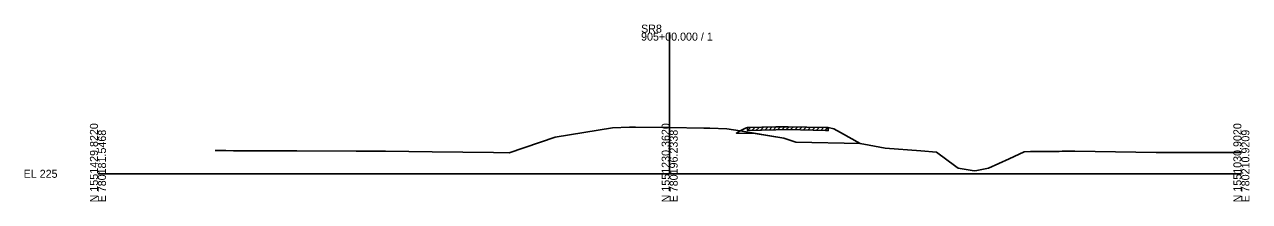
# Model space of a CAD drawing. Extents: x -26 to 787523, y -10 to 1545496.
# Drawn here: x -25.7 to 402.8, y 9990.3 to 10052.2 of the extents above; entities that cross this region are included whole.
import ezdxf

# ---------------------------------------------------------------- set-up
doc = ezdxf.new("R2010")
doc.units = 0
for name, color, linetype in [('50', 7, 'Continuous'), ('XS_CELL', 7, 'Continuous'), ('XS_M_SHAPES_EARTHWORK', 7, 'Continuous'), ('XS_P_FINISHED_GRADE', 7, 'Continuous'), ('XS_P_SUBGRADE_GRANULAR', 7, 'Continuous'), ('XS_X_GROUND', 7, 'Continuous')]:
    doc.layers.add(name, color=color, linetype=linetype)

msp = doc.modelspace()

# ---------------------------------------------------------------- linework, layer by layer
at = {"layer": '50'}
for p, q in [((227.24, 10015.13), (228.27, 10016.15)), ((227.24, 10015.13), (227.24, 10016.13)), ((227.24, 10015.13), (237.17, 10015.36)), ((228.74, 10015.16), (229.77, 10016.19)), ((230.25, 10015.2), (231.28, 10016.22)), ((231.75, 10015.23), (232.78, 10016.26)), ((233.26, 10015.27), (234.29, 10016.29)), ((234.76, 10015.3), (235.79, 10016.32)), ((236.27, 10015.33), (237.3, 10016.36)), ((237.17, 10015.36), (241.48, 10015.45)), ((237.78, 10015.37), (238.8, 10016.39)), ((239.28, 10015.4), (240.31, 10016.43)), ((240.79, 10015.44), (241.8, 10016.45)), ((241.48, 10015.45), (254.57, 10015.15)), ((242.29, 10015.43), (243.27, 10016.41)), ((243.8, 10015.4), (244.78, 10016.38)), ((245.3, 10015.36), (246.28, 10016.34)), ((246.81, 10015.33), (247.79, 10016.31)), ((248.31, 10015.29), (249.29, 10016.27)), ((249.82, 10015.26), (250.8, 10016.24)), ((251.32, 10015.22), (252.3, 10016.2)), ((252.83, 10015.19), (253.81, 10016.17)), ((254.33, 10015.15), (255.31, 10016.13)), ((254.57, 10015.15), (255.45, 10015.13)), ((255.45, 10016.13), (255.45, 10015.13))]:
    msp.add_line(p, q, dxfattribs=at)
at = {"layer": 'XS_CELL'}
for p, q in [((200, 10000), (200, 10049.36)), ((0, 10000), (200, 10000)), ((200, 10000), (400, 10000))]:
    msp.add_line(p, q, dxfattribs=at)
at = {"layer": 'XS_M_SHAPES_EARTHWORK'}
for points in [[(224.64, 10014.96), (229.95, 10014.07), (223.37, 10014.25)], [(224.64, 10014.96), (229.95, 10014.07), (223.37, 10014.25)], [(229.95, 10014.07), (239.95, 10012.41), (244.13, 10011.02), (266.62, 10010.57), (259.82, 10014.41), (257.46, 10015.74), (255.45, 10016.13), (255.45, 10015.13), (254.57, 10015.15), (241.48, 10015.45), (237.17, 10015.36), (227.24, 10015.13), (227.24, 10016.13), (226.55, 10015.91), (226.05, 10015.75), (224.64, 10014.96)], [(255.45, 10016.13), (257.46, 10015.74), (259.82, 10014.41), (266.62, 10010.57), (244.13, 10011.02), (239.95, 10012.41), (229.95, 10014.07), (224.64, 10014.96), (226.05, 10015.75), (226.55, 10015.91), (227.24, 10016.13), (227.24, 10015.13), (237.17, 10015.36), (241.48, 10015.45), (254.57, 10015.15), (255.45, 10015.13)], [(241.48, 10016.45), (254.57, 10016.15), (255.45, 10016.13), (255.45, 10015.13), (254.57, 10015.15), (241.48, 10015.45), (237.17, 10015.36), (227.24, 10015.13), (227.24, 10016.13), (237.17, 10016.36)], [(254.57, 10016.15), (255.45, 10016.13), (255.45, 10015.13), (254.57, 10015.15), (241.48, 10015.45), (237.17, 10015.36), (227.24, 10015.13), (227.24, 10016.13), (237.17, 10016.36), (241.48, 10016.45)]]:
    msp.add_lwpolyline(points, close=True, dxfattribs=at)
at = {"layer": 'XS_P_FINISHED_GRADE'}
for p, q in [((224.64, 10014.96), (239.95, 10012.41)), ((239.95, 10012.41), (244.13, 10011.02)), ((266.62, 10010.57), (244.13, 10011.02))]:
    msp.add_line(p, q, dxfattribs=at)
at = {"layer": 'XS_P_SUBGRADE_GRANULAR'}
for q in [(224.64, 10014.96), (229.95, 10014.07)]:
    msp.add_line((223.37, 10014.25), q, dxfattribs=at)
at = {"layer": 'XS_X_GROUND'}
for p, q in [((160, 10012.77), (180, 10016.11)), ((180, 10016.11), (186, 10016.35)), ((186, 10016.35), (188, 10016.32)), ((188, 10016.32), (200, 10016.16)), ((200, 10016.16), (212, 10016)), ((212, 10016), (214, 10015.97)), ((214, 10015.97), (220, 10015.73)), ((220, 10015.73), (224.64, 10014.96)), ((224.64, 10014.96), (226.05, 10015.75)), ((226.05, 10015.75), (226.55, 10015.91)), ((226.55, 10015.91), (227.24, 10016.13)), ((227.24, 10016.13), (237.17, 10016.36)), ((237.17, 10016.36), (241.48, 10016.45)), ((241.48, 10016.45), (254.57, 10016.15)), ((254.57, 10016.15), (255.45, 10016.13)), ((255.45, 10016.13), (257.46, 10015.74)), ((257.46, 10015.74), (259.82, 10014.41)), ((143.83, 10007.38), (160, 10012.77)), ((259.82, 10014.41), (266.62, 10010.57)), ((266.62, 10010.57), (269.74, 10010)), ((40.96, 10008.11), (44.68, 10008.09)), ((44.68, 10008.09), (47.41, 10008.08)), ((47.41, 10008.08), (61.51, 10008.02)), ((61.51, 10008.02), (69.55, 10007.98)), ((69.55, 10007.98), (90.31, 10007.89)), ((90.31, 10007.89), (93.01, 10007.88)), ((93.01, 10007.88), (94.55, 10007.87)), ((94.55, 10007.87), (100.58, 10007.85)), ((100.58, 10007.85), (116.91, 10007.67)), ((116.91, 10007.67), (138.35, 10007.4)), ((138.35, 10007.4), (143.83, 10007.38)), ((269.74, 10010), (275.37, 10009.01)), ((275.37, 10009.01), (287.85, 10008)), ((287.85, 10008), (293.34, 10007.56)), ((293.34, 10007.56), (300.13, 10002.5)), ((318.77, 10005.28), (323.99, 10007.72)), ((323.99, 10007.72), (326.2, 10007.74)), ((326.2, 10007.74), (332.1, 10007.8)), ((332.1, 10007.8), (334.76, 10007.83)), ((334.76, 10007.83), (336.28, 10007.84)), ((336.28, 10007.84), (337.26, 10007.85)), ((337.26, 10007.85), (341.68, 10007.91)), ((341.68, 10007.91), (370.19, 10007.47)), ((370.19, 10007.47), (378.92, 10007.45)), ((378.92, 10007.45), (398.45, 10007.47)), ((398.45, 10007.47), (400, 10007.46)), ((300.13, 10002.5), (300.91, 10001.94)), ((311.55, 10001.92), (318.77, 10005.28)), ((300.91, 10001.94), (305.85, 10001.12)), ((305.85, 10001.12), (306.65, 10000.98)), ((306.65, 10000.98), (307.48, 10001.15)), ((307.48, 10001.15), (311.55, 10001.92))]:
    msp.add_line(p, q, dxfattribs=at)

# ---------------------------------------------------------------- texts
at = {"layer": 'XS_CELL'}
for s, p in [('SR8', (190, 10049.36)), ('905+00.000 / 1', (190, 10046.56)), ('EL 225', (-26, 9998.6))]:
    msp.add_text(s, height=2.8, dxfattribs=at).set_placement(p)
for s, p in [('N 1551429.8220', (0, 9990)), ('E 780181.5468', (2.8, 9990)), ('N 1551230.3620', (200, 9990)), ('E 780196.2338', (202.8, 9990)), ('N 1551030.9020', (400, 9990)), ('E 780210.9209', (402.8, 9990))]:
    msp.add_text(s, height=2.8, rotation=90, dxfattribs=at).set_placement(p)

doc.saveas('drawing.dxf')
